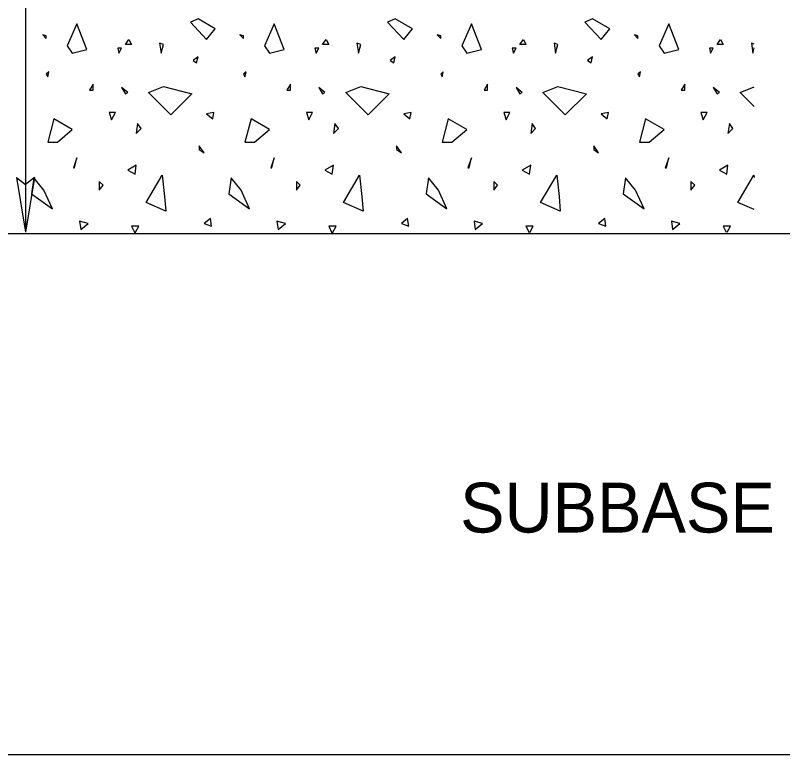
# Model space of a CAD drawing. Extents: x 2.92 to 10.05, y 1.3 to 10.63.
# Drawn here: x 5.949 to 6.873, y 5.922 to 6.811 of the extents above; entities that cross this region are included whole.
import ezdxf

# ---------------------------------------------------------------- set-up
doc = ezdxf.new("R2010")
doc.units = 0
for name, color, linetype in [('DETL-DIMS', 7, 'Continuous'), ('DETL-LINE', 7, 'Continuous'), ('DETL-NOTE', 7, 'Continuous'), ('DETL-PATT', 7, 'Continuous')]:
    doc.layers.add(name, color=color, linetype=linetype)

msp = doc.modelspace()

# ---------------------------------------------------------------- linework, layer by layer
at = {"layer": 'DETL-DIMS'}
for p, q in [((5.96086, 6.95945), (5.96086, 6.55035)), ((5.94988, 6.61624), (5.96086, 6.55035)), ((5.94988, 6.61624), (5.96086, 6.608)), ((5.97184, 6.61624), (5.96086, 6.55035)), ((5.97184, 6.61624), (5.96086, 6.608))]:
    msp.add_line(p, q, dxfattribs=at)
at = {"layer": 'DETL-LINE'}
for p, q in [((3.60141, 6.54902), (7.87612, 6.54902)), ((3.60141, 5.92157), (7.87612, 5.92157))]:
    msp.add_line(p, q, dxfattribs=at)
at = {"layer": 'DETL-PATT'}
for points in [[(6.01718, 6.76573), (6.03482, 6.77031), (6.02282, 6.80137), (6.01118, 6.7749)], [(6.15941, 6.80314), (6.17882, 6.78231), (6.18941, 6.79537), (6.16859, 6.80737)], [(6.25471, 6.76573), (6.27235, 6.77031), (6.26035, 6.80137), (6.24871, 6.7749)], [(6.39694, 6.80314), (6.41635, 6.78231), (6.42694, 6.79537), (6.40612, 6.80737)], [(6.49224, 6.76573), (6.50988, 6.77031), (6.49788, 6.80137), (6.48624, 6.7749)], [(6.63447, 6.80314), (6.65388, 6.78231), (6.66447, 6.79537), (6.64365, 6.80737)], [(6.72976, 6.76573), (6.74741, 6.77031), (6.73541, 6.80137), (6.72376, 6.7749)], [(5.98576, 6.78655), (5.98153, 6.78796), (5.98576, 6.78373)], [(6.22329, 6.78655), (6.21906, 6.78796), (6.22329, 6.78373)], [(6.46082, 6.78655), (6.45659, 6.78796), (6.46082, 6.78373)], [(6.69835, 6.78655), (6.69412, 6.78796), (6.69835, 6.78373)], [(6.08529, 6.78231), (6.08847, 6.77631), (6.08106, 6.77631)], [(6.12235, 6.77773), (6.12412, 6.76573), (6.12694, 6.77631)], [(6.32282, 6.78231), (6.326, 6.77631), (6.31859, 6.77631)], [(6.35988, 6.77773), (6.36165, 6.76573), (6.36447, 6.77631)], [(6.56035, 6.78231), (6.56353, 6.77631), (6.55612, 6.77631)], [(6.59741, 6.77773), (6.59918, 6.76573), (6.602, 6.77631)], [(6.79788, 6.78231), (6.80106, 6.77631), (6.79365, 6.77631)], [(6.07188, 6.77173), (6.07329, 6.76573), (6.07647, 6.77173)], [(6.30941, 6.77173), (6.31082, 6.76573), (6.314, 6.77173)], [(6.54694, 6.77173), (6.54835, 6.76573), (6.55153, 6.77173)], [(6.78447, 6.77173), (6.78588, 6.76573), (6.78906, 6.77173)], [(6.16259, 6.7569), (6.16682, 6.75408), (6.16859, 6.76149)], [(6.40012, 6.7569), (6.40435, 6.75408), (6.40612, 6.76149)], [(6.63765, 6.7569), (6.64188, 6.75408), (6.64365, 6.76149)], [(5.98894, 6.74349), (5.98576, 6.74067), (5.98753, 6.73749)], [(6.22647, 6.74349), (6.22329, 6.74067), (6.22506, 6.73749)], [(6.464, 6.74349), (6.46082, 6.74067), (6.46259, 6.73749)], [(6.70153, 6.74349), (6.69835, 6.74067), (6.70012, 6.73749)], [(6.04224, 6.72867), (6.038, 6.72125), (6.04224, 6.72125)], [(6.27976, 6.72867), (6.27553, 6.72125), (6.27976, 6.72125)], [(6.51729, 6.72867), (6.51306, 6.72125), (6.51729, 6.72125)], [(6.75482, 6.72867), (6.75059, 6.72125), (6.75482, 6.72125)], [(6.08106, 6.71702), (6.08388, 6.71843), (6.07647, 6.72443)], [(6.12694, 6.72584), (6.16118, 6.71702), (6.13576, 6.69161), (6.10894, 6.71843)], [(6.31859, 6.71702), (6.32141, 6.71843), (6.314, 6.72443)], [(6.36447, 6.72584), (6.39871, 6.71702), (6.37329, 6.69161), (6.34647, 6.71843)], [(6.55612, 6.71702), (6.55894, 6.71843), (6.55153, 6.72443)], [(6.602, 6.72584), (6.63624, 6.71702), (6.61082, 6.69161), (6.584, 6.71843)], [(6.79365, 6.71702), (6.79647, 6.71843), (6.78906, 6.72443)], [(6.06165, 6.69443), (6.06447, 6.68561), (6.06906, 6.69443)], [(6.17882, 6.69302), (6.18624, 6.68702), (6.18765, 6.69443)], [(6.29918, 6.69443), (6.302, 6.68561), (6.30659, 6.69443)], [(6.41635, 6.69302), (6.42376, 6.68702), (6.42518, 6.69443)], [(6.53671, 6.69443), (6.53953, 6.68561), (6.54412, 6.69443)], [(6.65388, 6.69302), (6.66129, 6.68702), (6.66271, 6.69443)], [(6.77424, 6.69443), (6.77706, 6.68561), (6.78165, 6.69443)], [(5.99918, 6.65878), (6.01718, 6.67396), (5.99494, 6.68702), (5.98753, 6.65878)], [(6.09588, 6.68137), (6.09412, 6.66937), (6.10012, 6.67537)], [(6.23671, 6.65878), (6.25471, 6.67396), (6.23247, 6.68702), (6.22506, 6.65878)], [(6.33341, 6.68137), (6.33165, 6.66937), (6.33765, 6.67537)], [(6.47424, 6.65878), (6.49224, 6.67396), (6.47, 6.68702), (6.46259, 6.65878)], [(6.57094, 6.68137), (6.56918, 6.66937), (6.57518, 6.67537)], [(6.71176, 6.65878), (6.72976, 6.67396), (6.70753, 6.68702), (6.70012, 6.65878)], [(6.80847, 6.68137), (6.80671, 6.66937), (6.81271, 6.67537)], [(6.17, 6.65455), (6.17, 6.64996), (6.176, 6.64573)], [(6.40753, 6.65455), (6.40753, 6.64996), (6.41353, 6.64573)], [(6.64506, 6.65455), (6.64506, 6.64996), (6.65106, 6.64573)], [(6.01859, 6.62773), (6.02, 6.62773), (6.02282, 6.63973)], [(6.25612, 6.62773), (6.25753, 6.62773), (6.26035, 6.63973)], [(6.49365, 6.62773), (6.49506, 6.62773), (6.49788, 6.63973)], [(6.73118, 6.62773), (6.73259, 6.62773), (6.73541, 6.63973)], [(6.08388, 6.6249), (6.09271, 6.62031), (6.09412, 6.6309)], [(6.32141, 6.6249), (6.33024, 6.62031), (6.33165, 6.6309)], [(6.55894, 6.6249), (6.56776, 6.62031), (6.56918, 6.6309)], [(6.79647, 6.6249), (6.80529, 6.62031), (6.80671, 6.6309)], [(6.12835, 6.59349), (6.12976, 6.57584), (6.10612, 6.58608), (6.12553, 6.6189)], [(6.36588, 6.59349), (6.36729, 6.57584), (6.34365, 6.58608), (6.36306, 6.6189)], [(6.60341, 6.59349), (6.60482, 6.57584), (6.58118, 6.58608), (6.60059, 6.6189)], [(5.97094, 6.61573), (5.96812, 6.59667), (5.99318, 6.57867), (5.98294, 6.6009)], [(6.04965, 6.61149), (6.04965, 6.6009), (6.05424, 6.6069)], [(6.20847, 6.61573), (6.20565, 6.59667), (6.23071, 6.57867), (6.22047, 6.6009)], [(6.28718, 6.61149), (6.28718, 6.6009), (6.29176, 6.6069)], [(6.446, 6.61573), (6.44318, 6.59667), (6.46824, 6.57867), (6.458, 6.6009)], [(6.52471, 6.61149), (6.52471, 6.6009), (6.52929, 6.6069)], [(6.68353, 6.61573), (6.68071, 6.59667), (6.70576, 6.57867), (6.69553, 6.6009)], [(6.76224, 6.61149), (6.76224, 6.6009), (6.76682, 6.6069)], [(6.026, 6.56384), (6.02741, 6.55361), (6.03624, 6.56102)], [(6.18341, 6.56702), (6.176, 6.56102), (6.18482, 6.55784)], [(6.26353, 6.56384), (6.26494, 6.55361), (6.27376, 6.56102)], [(6.42094, 6.56702), (6.41353, 6.56102), (6.42235, 6.55784)], [(6.50106, 6.56384), (6.50247, 6.55361), (6.51129, 6.56102)], [(6.65847, 6.56702), (6.65106, 6.56102), (6.65988, 6.55784)], [(6.73859, 6.56384), (6.74, 6.55361), (6.74882, 6.56102)]]:
    msp.add_lwpolyline(points, close=True, dxfattribs=at)
for points in [[(6.83843, 6.77667), (6.83494, 6.77773), (6.83671, 6.76573), (6.83843, 6.7722)], [(6.83843, 6.70153), (6.82153, 6.71843), (6.83843, 6.72537)], [(6.83843, 6.57753), (6.81871, 6.58608), (6.83812, 6.6189), (6.83843, 6.61608)], [(6.09298, 6.54957), (6.09729, 6.55784), (6.08847, 6.55784), (6.09247, 6.54953)], [(6.33063, 6.5498), (6.33482, 6.55784), (6.326, 6.55784), (6.32984, 6.5498)], [(6.56831, 6.55008), (6.57235, 6.55784), (6.56353, 6.55784), (6.56725, 6.55008)], [(6.80596, 6.55031), (6.80988, 6.55784), (6.80106, 6.55784), (6.80467, 6.55031)]]:
    msp.add_lwpolyline(points, dxfattribs=at)

# ---------------------------------------------------------------- texts
at = {"layer": 'DETL-NOTE'}
msp.add_text('SUBBASE', height=0.06, dxfattribs=at).set_placement((6.4842, 6.1889))

doc.saveas('drawing.dxf')
